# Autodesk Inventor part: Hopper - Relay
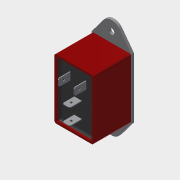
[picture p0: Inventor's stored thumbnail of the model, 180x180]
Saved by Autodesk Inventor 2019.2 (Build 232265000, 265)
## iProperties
Created: 2005-11
Part Number: Hopper - Relay
Document SubType Name: Modeling
Designer: floress
Material: Default
Density: 1 g/cm^3
Appearance: Default
Author: floress
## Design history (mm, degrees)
sketch "Sketch1"
  geometry: L1 (-8.058, 30.818)-(17.342, 30.818); L2 (17.342, 30.818)-(17.342, -7.282); L3 (17.342, -7.282)-(-8.058, -7.282); L4 (-8.058, -7.282)-(-8.058, 30.818)
  constraints: 8 end point, 2 parallel, 1 horizontal, 1 perpendicular
  dimensions: "d0" = 25.4 distance of L2.end L3.end; "d1" = 38.1 distance of L3.end L1.start
extrude "Extrusion1" new body sketch "Sketch1" distance "d2" = 25.4; taper "d3" = 0 deg
sketch "Sketch2"
  geometry: L1 (17.342, 30.818)-(17.342, -7.282) reference; L2 (-8.058, 30.818)-(17.342, 30.818) reference; L3 (-8.058, -7.282)-(-8.058, 30.818) reference; L4 (17.342, -7.282)-(-8.058, -7.282) reference; L5 (-6.534, 29.548)-(15.818, 29.548); L6 (15.818, 29.548)-(15.818, -6.012); L7 (15.818, -6.012)-(-6.534, -6.012); L8 (-6.534, -6.012)-(-6.534, 29.548)
  constraints: 8 end point, 2 parallel, 1 horizontal, 1 perpendicular
  dimensions: "d4" = 1.524 distance between parallel lines of L3 L8; "d5" = 1.27 distance between parallel lines of L2 L5; "d6" = 1.524 distance between parallel lines of L1 L6; "d7" = 1.27 distance between parallel lines of L4 L7
extrude "Extrusion2" cut sketch "Sketch2" distance "d8" = 2.54; taper "d9" = 0 deg
sketch "Sketch3"
  geometry: L1 (8.058, 30.818)-(-17.342, 30.818) reference; L2 (-17.342, 30.818)-(-17.342, -7.282) reference; L3 (8.058, -7.282)-(8.058, 30.818) reference; L4 (-17.342, 30.818)-(-9.722, 40.978); L5 (8.058, 30.818)-(0.438, 40.978); L6 (-17.342, 11.768)-(8.058, 11.768); L7 (8.058, -7.282)-(-17.342, -7.282); L8 (-17.342, -7.282)-(-9.722, -17.442); L9 (8.058, -7.282)-(0.438, -17.442); C1 r 1.778 at (-4.642, 37.168); C2 r 1.778 at (-4.642, -13.632); A1 r 6.35 centre (-4.642, 37.168) between (0.438, 40.978) and (-9.722, 40.978); A2 r 6.35 centre (-4.642, -13.632) between (-9.722, -17.442) and (0.438, -17.442)
  constraints: 12 end point, 4 centre point, 4 point on circle, 4 symmetric about line, 3 tangent, 2 coincident, 2 midpoint, 2 other
  dimensions: "d10" = 12.7 diameter of A1; "d11" = 3.556 diameter of C1
extrude "Extrusion3" join sketch "Sketch3" distance "d12" = 1.5875; taper "d13" = 0 deg
sketch "Sketch4"
  geometry: L1 (-6.534, -6.012)-(15.818, -6.012) reference; L2 (15.818, 29.548)-(-6.534, 29.548) reference; L3 (-0.629, 23.198)-(-0.121, 23.198); L4 (-0.121, 23.198)-(-0.121, 18.449); L5 (-0.121, 18.449)-(-0.629, 18.449); L6 (-0.629, 18.449)-(-0.629, 23.198); L7 (9.404, 23.198)-(9.912, 23.198); L8 (9.912, 23.198)-(9.912, 18.449); L9 (9.912, 18.449)-(9.404, 18.449); L10 (9.404, 18.449)-(9.404, 23.198); L11 (2.267, 10.879)-(7.017, 10.879); L12 (7.017, 10.879)-(7.017, 10.371); L13 (7.017, 10.371)-(2.267, 10.371); L14 (2.267, 10.371)-(2.267, 10.879); L15 (2.267, 0.846)-(7.017, 0.846); L16 (7.017, 0.846)-(7.017, 0.338); L17 (7.017, 0.338)-(2.267, 0.338); L18 (2.267, 0.338)-(2.267, 0.846); L19 (-0.121, 20.824)-(9.404, 20.824); 3 further points
  constraints: 34 end point, 8 parallel, 6 equal length, 5 midpoint, 4 horizontal, 4 perpendicular, 3 vertical alignment, 1 horizontal alignment
  dimensions: "d14" = 4.7498 distance of L5.end L3.start; "d15" = 0.508 distance of L4.end L5.end; "d16" = 9.525 distance between parallel lines of L15 L13; "d17" = 9.525 distance between parallel lines of L4 L10; "d18" = 6.35 distance between parallel lines of L1 L17; "d19" = 6.35 distance from line of L7.start L2
extrude "Extrusion4" join sketch "Sketch4" distance "d20" = 7.62; taper "d21" = 0 deg
fillet "Fillet1" dims "d22" = 1.27
sketch "Sketch5"
  geometry: L1 (0, 38.1)-(-23.812, 38.1); L2 (-23.812, 38.1)-(-23.812, 0); L3 (-23.812, 0)-(0, 0); L4 (0, 0)-(0, 38.1)
  constraints: 8 end point, 2 parallel, 1 horizontal, 1 perpendicular
extrude "Extrusion5" cut sketch "Sketch5" distance "d24" = 0.254; taper "d25" = 0 deg
sketch "Sketch6"
  geometry: L1 (23.812, 38.1)-(23.812, 0) reference; L2 (0, 0)-(23.812, 0) reference; L3 (0, 38.1)-(0, 0) reference; L4 (23.812, 38.1)-(0, 38.1) reference
extrude "Extrusion6" cut sketch "Sketch6" distance "d26" = 0.254; taper "d27" = 0 deg
fillet "Fillet3" dims "d28" = 1.27
chamfer "Chamfer1" distance "d29" = 0.2032; stored, may be unused: second distance "d30" = 3.175, angle "d31" = 45 deg
chamfer "Chamfer2" distance "d32" = 0.79375; stored, may be unused: second distance "d33" = 3.175, angle "d34" = 45 deg
sketch "Sketch7"
  geometry: L1 (-7.417, 0.591)-(-7.417, 4.159) reference; C1 r 0.698 at (-4.242, 2.375); 1 further point
  constraints: 1 centre point, 1 horizontal alignment, 1 midpoint
  dimensions: "d35" = 1.397 diameter of C1; "d36" = 3.175 distance from line of L1 C1.centre
extrude "Extrusion7" cut sketch "Sketch7" extent not by distance; stored distance "d37" = 0.254; taper "d38" = 0 deg
sketch "Sketch8"
  geometry: L1 (4.159, -7.417)-(0.591, -7.417) reference; C1 r 0.698 at (2.375, -4.242); 1 further point
  constraints: 1 centre point, 1 midpoint, 1 vertical alignment
  dimensions: "d39" = 1.397 diameter of C1; "d40" = 3.175 distance from line of L1 C1.centre
extrude "Extrusion8" cut sketch "Sketch8" extent not by distance; stored distance "d41" = 0.254; taper "d42" = 0 deg
body "Solid1"
node "Projected Loop1"
